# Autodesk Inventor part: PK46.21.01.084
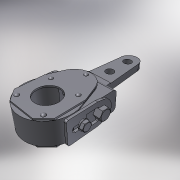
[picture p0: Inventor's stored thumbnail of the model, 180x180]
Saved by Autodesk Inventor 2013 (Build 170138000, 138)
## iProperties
Created: 2005-03
Part Number: PK46.21.01.084
Material: Steel, Mild
Document SubType Name: Modeling
Designer: salex
Manufacturer: Standard
Standards Organization: Custom
Density: 7.86 g/cm^3
Mass: 2145.62 g
Surface Area: 686.057 cm^2
Volume: 272.98 cm^3
Author: salex
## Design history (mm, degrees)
feature "Sculpt1"
body "Solid2"
feature "Surface1"
body "Srf1"
